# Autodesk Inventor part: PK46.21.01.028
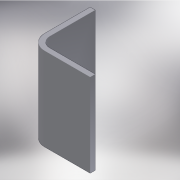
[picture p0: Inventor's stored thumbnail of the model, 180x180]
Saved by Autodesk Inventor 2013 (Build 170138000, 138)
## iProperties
Created: 2005-04
Part Number: PK46.21.01.028
Material: Steel, Mild
Document SubType Name: Sheet Metal
Designer: salex
Manufacturer: Standard
Standards Organization: Custom
Density: 7.86 g/cm^3
Sheet Metal Rule: Default
Author: salex
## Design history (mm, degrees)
node "ФлнОтгиб1"
body "Solid1"
sketch "Эскиз1"
  geometry: L1 (0, 0)-(0, -110); L2 (0, -110)-(110, -110)
  constraints: 4 end point, 1 perpendicular, 1 vertical, 1 other
  dimensions: "d0" = 110 distance of L1.start L1.end; "d1" = 110 distance of L1.end L2.end
feature "Плакирование1" dims "d2" = 165, "d3" = 10 (= BendReliefWidth), "d5" = 20 (= MinimumRemnant), "d7" = 20 (= BendRadius), "d8" = 10, "Thickness" = 10
feature "Изгиб1" dims "d3" = 10 (= BendReliefWidth), "d4" = 5 (= BendReliefDepth), "d5" = 20 (= MinimumRemnant), "d6" = 20 (= BendRadius), "d7" = 20 (= BendRadius), "d8" = 10, "SeamGap" = 0.01, "Thickness" = 10
other parameters: "BendRadius" = 20, "BendReliefDepth" = 5 (= 0.5 x Thickness)
